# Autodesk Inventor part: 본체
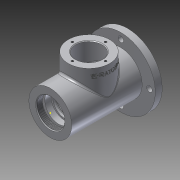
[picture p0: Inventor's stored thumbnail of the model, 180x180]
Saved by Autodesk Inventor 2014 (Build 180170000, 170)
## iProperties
Created: 2016-08
Part Number: 본체
Material: 알루미늄 6061
Document SubType Name: Modeling
Designer: owner
Density: 2.71 g/cm^3
Appearance: 알루미늄 - 평지
Mass: 735.756 g
Surface Area: 625.438 cm^2
Volume: 271.497 cm^3
Author: owner
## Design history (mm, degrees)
sketch "스케치1"
  geometry: C1 r 31 at (0, 0); 1 further point
  constraints: 1 centre point, 1 coincident
  dimensions: "d0" = 62 diameter of C1
extrude "돌출1" new body sketch "스케치1" distance "d1" = 102; taper "d2" = 0 deg
sketch "스케치2"
  geometry: C1 r 31 at (0, 0) reference; C2 r 50 at (0, 0)
  constraints: 1 centre point, 1 coincident
  dimensions: "d3" = 100 diameter of C2
extrude "돌출2" join sketch "스케치2" distance "d4" = 13; taper "d5" = 0 deg
sketch "스케치3"
  geometry: C1 r 31 at (0, 0) reference
hole "구멍1" sketch "스케치3" at (0, 0) diameter "d6" = 40.376; stored, may be unused: countersink angle "d10" = 90 deg, drill point angle "d12" = 0 deg; dims "d7" = 6, "d8" = 4, "d9" = 2, "d11" = 9
node "작업 평면1"
sketch "스케치14"
  geometry: C1 r 30 at (0, 56); 1 further point
  constraints: 1 centre point, 1 vertical alignment
  dimensions: "d77" = 60 diameter of C1; "d78" = 56 distance of C1.centre point (0, 0)
extrude "돌출3" join sketch "스케치14" stored distance "d79" = 14; taper "d80" = 0 deg
sketch "스케치15" dims "d81" = 48
  geometry: C1 r 30 at (0, 0) reference; 3 further points
  constraints: 2 horizontal alignment, 1 coincident, 2 other
hole "구멍11" sketch "스케치15" at (24, 0) diameter "d82" = 3.242; stored, may be unused: countersink angle "d86" = 90 deg, drill point angle "d88" = 118 deg; dims "d83" = 8, "d84" = 48, "d85" = 3, "d87" = 10
sketch "스케치16"
  geometry: C1 r 30 at (0, 0) reference; C2 r 19 at (0, 0); 1 further point
  constraints: 1 centre point, 1 coincident
  dimensions: "d92" = 38 diameter of C2
extrude "돌출4" cut sketch "스케치16" distance "d93" = 50; taper "d94" = 0 deg
sketch "스케치17"
  geometry: 1 further point
sketch "스케치18"
  geometry: C1 r 20.188 at (0, 0) reference
hole "구멍12" sketch "스케치18" at (0, 0) diameter "d95" = 48; stored, may be unused: countersink angle "d99" = 90 deg, drill point angle "d101" = 0 deg; dims "d96" = 8, "d97" = 48, "d98" = 3, "d100" = 3
sketch "스케치19"
  geometry: C1 r 24 at (0, 0) reference; C2 r 20 at (0, 0)
  constraints: 1 centre point, 1 coincident
  dimensions: "d102" = 40 diameter of C2
hole "구멍13" sketch "스케치19" at (0, 0) diameter "d103" = 40; stored, may be unused: countersink angle "d107" = 90 deg, drill point angle "d109" = 0 deg; dims "d104" = 8, "d105" = 48, "d106" = 3, "d108" = 9
sketch "스케치20"
  geometry: C1 r 20 at (0, 0) reference
hole "구멍14" sketch "스케치20" at (0, 0) diameter "d110" = 35; stored, may be unused: countersink angle "d114" = 90 deg, drill point angle "d116" = 0 deg; dims "d111" = 8, "d112" = 35, "d113" = 3.25, "d115" = 3.25
sketch "스케치21"
  geometry: C1 r 17.5 at (0, 0) reference
hole "구멍15" sketch "스케치21" at (0, 0) diameter "d117" = 37; stored, may be unused: countersink angle "d121" = 90 deg, drill point angle "d123" = 0 deg; dims "d118" = 8, "d119" = 35, "d120" = 3.25, "d122" = 1.75
sketch "스케치22"
  geometry: C1 r 18.5 at (0, 0) reference
hole "구멍16" sketch "스케치22" at (0, 0) diameter "d124" = 35; stored, may be unused: countersink angle "d128" = 90 deg, drill point angle "d130" = 0 deg; dims "d125" = 8, "d126" = 35, "d127" = 3.25, "d129" = 11
sketch "스케치23"
  geometry: A1 r 17.5 centre (0, 0) between (-17.5, 0) and (-17.5, 0) reference
hole "구멍17" sketch "스케치23" at (0, 0) diameter "d131" = 52; stored, may be unused: countersink angle "d135" = 90 deg, drill point angle "d137" = 0 deg; dims "d132" = 8, "d133" = 35, "d134" = 3.25, "d136" = 38
sketch "스케치24"
  geometry: A1 r 26 centre (0, 0) between (26, 0) and (26, 0) reference
hole "구멍18" sketch "스케치24" at (0, 0) diameter "d138" = 35; stored, may be unused: countersink angle "d142" = 90 deg, drill point angle "d144" = 0 deg; dims "d139" = 8, "d140" = 35, "d141" = 3.25, "d143" = 11
sketch "스케치25"
  geometry: C1 r 17.5 at (0, 0) reference
hole "구멍19" sketch "스케치25" at (0, 0) diameter "d145" = 33; stored, may be unused: countersink angle "d149" = 90 deg, drill point angle "d151" = 0 deg; dims "d146" = 8, "d147" = 35, "d148" = 3.25, "d150" = 5
sketch "스케치26"
  geometry: C1 r 16.5 at (0, 0) reference
hole "구멍20" sketch "스케치26" at (0, 0) diameter "d152" = 20; stored, may be unused: countersink angle "d156" = 90 deg, drill point angle "d158" = 0 deg; dims "d153" = 8, "d154" = 35, "d155" = 3.25, "d157" = 2.7
sketch "스케치27"
  geometry: C1 r 10 at (0, 0) reference
hole "구멍21" sketch "스케치27" at (0, 0) diameter "d159" = 25; stored, may be unused: countersink angle "d163" = 90 deg, drill point angle "d165" = 0 deg; dims "d160" = 8, "d161" = 35, "d162" = 3.25, "d164" = 6.6
sketch "스케치30"
  geometry: L1 (-12.5, 100.3)-(12.5, 100.3) reference; 3 further points
  constraints: 2 coincident, 1 midpoint
sketch "스케치31"
  geometry: C1 r 12.5 at (0, 0) reference
hole "구멍23" sketch "스케치31" at (0, 0) diameter "d177" = 25; stored, may be unused: countersink angle "d181" = 90 deg, drill point angle "d183" = 0 deg; dims "d178" = 8, "d179" = 35, "d180" = 3.25, "d182" = 0.7
sketch "스케치32"
  geometry: L1 (-12.5, 101)-(12.5, 101) reference; L2 (-12.917, 101)-(-21, 115); L3 (0, 101)-(0, 115); L4 (50, 115)-(-50, 115) reference; L5 (-12.917, 101)-(-12.5, 101); L6 (-21, 115)-(0, 115); L7 (-12.5, 101)-(0, 101); 1 further point
  constraints: 10 end point, 2 midpoint, 2 perpendicular, 2 point on line, 1 collinear
  dimensions: "d184" = 42 diameter of L2.end L3; "d185" = 60 deg angle of L4 L2
revolve "회전1" sketch "스케치32" stored, may be unused: angle "d186" = 90 deg
node "작업 평면2"
sketch "스케치33"
  geometry: L1 (18, -56)-(80, -56) reference; L2 (0, -30)-(0, 30) reference; 2 further points
  constraints: 1 other
  dimensions: "d187" = 56 distance from line of point (10, 0) L1; "d188" = 10 distance from line of point (10, 0) L2
feature "엠보싱1" sketch "스케치33" dims "d0" = 62, "d189" = 0.5, "d190" = 0
sketch "스케치34" dims "d191" = 83
  geometry: C1 r 50 at (0, 0) reference; 2 further points
  constraints: 2 horizontal alignment, 1 coincident, 2 other
hole "구멍24" sketch "스케치34" at (41.5, 0) diameter "d192" = 8; stored, may be unused: countersink angle "d196" = 90 deg, drill point angle "d198" = 0 deg; dims "d193" = 8, "d194" = 35, "d195" = 3.25, "d197" = 16
sketch "스케치35"
  geometry: C1 r 4 at (0, -41.5) reference; C2 r 4 at (-41.5, 0) reference; C3 r 4 at (0, 41.5) reference; C4 r 4 at (41.5, 0) reference; C5 r 50 at (0, 0) reference; C6 r 31 at (0, 0)
  constraints: 1 centre point, 1 coincident
  dimensions: "d202" = 62 diameter of C6
extrude "돌출5" cut sketch "스케치35" distance "d203" = 3; taper "d204" = 0 deg
fillet "모깎기1" dims "d205" = 0.3
fillet "모깎기2" dims "d206" = 0.3
fillet "모깎기3" dims "d207" = 3
fillet "모깎기4" dims "d208" = 3
chamfer "모따기1" distance "d209" = 1; stored, may be unused: second distance "d210" = 2, angle "d211" = 45 deg
chamfer "모따기2" distance "d212" = 1; stored, may be unused: second distance "d213" = 2, angle "d214" = 45 deg
node "솔리드1"
pattern_circular "원형 패턴1" dims angle "d90" = 360 deg
pattern_circular "원형 패턴2" dims angle "d200" = 360 deg
other parameters: "d76" = 49
